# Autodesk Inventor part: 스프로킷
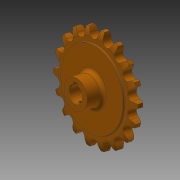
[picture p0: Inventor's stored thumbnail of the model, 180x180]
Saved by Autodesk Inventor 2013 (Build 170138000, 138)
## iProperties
Created: 2016-03
Part Number: 스프로킷
Material: 강철, 탄소
Document SubType Name: Modeling
Designer: mduedu
Density: 7.87 g/cm^3
Mass: 301.818 g
Surface Area: 124.882 cm^2
Volume: 38.3505 cm^3
Author: mduedu
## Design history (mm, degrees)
sketch "스케치1"
  geometry: L1 (0, 5)-(29.5, 5); L2 (29.5, 5)-(29.5, 4.1); L3 (30, 3.6)-(33.625, 3.6); L4 (40, 2)-(40, 0); L5 (40, 0)-(0, 0); L6 (0, 0)-(0, 5); L7 (0, -5)-(29.5, -5); L8 (29.5, -5)-(29.5, -4.1); L9 (30, -3.6)-(33.625, -3.6); L10 (40, -2)-(40, 0); L11 (0, 0)-(0, -5); A1 r 13.5 centre (33.625, -9.9) between (40, 2) and (33.625, 3.6); A2 r 13.5 centre (33.625, 9.9) between (33.625, -3.6) and (40, -2); A3 r 0.5 centre (30, 4.1) between (29.5, 4.1) and (30, 3.6); A4 r 0.5 centre (30, -4.1) between (30, -3.6) and (29.5, -4.1); 2 further points
  constraints: 22 end point, 8 point on circle, 6 symmetric about line, 5 tangent, 4 centre point, 4 parallel, 4 point on line, 1 equal radius, 1 horizontal, 1 perpendicular, 1 other
  dimensions: "d0" = 80 diameter of L4 L6; "d2" = 59 diameter of L2 L6; "d3" = 1.6 vertical distance of L4.start L3.end; "d4" = 3.6 distance from line of L4.end L3; "d5" = 5 distance between parallel lines of L5 L1; "d6" = 13.5 radius of A1; "d15" = 0.5 radius of A3
revolve "회전1" sketch "스케치1" stored, may be unused: angle "d7" = 90 deg
sketch "스케치2" dims "d8" = 65.2, "d11" = 80
  geometry: L1 (0, 0)-(0, 32.6); A1 r 36.57 centre (0, 0) between (-16.231, 32.771) and (0, 36.57); A2 r 3.97 centre (0, 36.57) between (-3.866, 35.665) and (0, 32.6); A3 r 12.7 centre (-16.231, 32.771) between (-3.866, 35.665) and (-5.534, 39.615); A4 r 12.7 centre (16.231, 32.771) between (5.534, 39.615) and (3.866, 35.665); A5 r 3.97 centre (0, 36.57) between (0, 32.6) and (3.866, 35.665); A6 r 40 centre (0, 0) between (5.534, 39.615) and (-5.534, 39.615); 2 further points
  constraints: 12 point on circle, 6 centre point, 4 coincident, 3 symmetric about line, 2 end point, 1 point on line, 1 tangent, 1 vertical, 1 vertical alignment, 7 other
  dimensions: "d10" = 73.14 diameter of A1; "d12" = 12.7 radius of A3
extrude "돌출1" cut sketch "스케치2" stored distance "d13" = 10; taper "d14" = 0 deg
sketch "스케치3"
  geometry: C1 r 11 at (0, 0); 1 further point
  constraints: 1 centre point, 1 coincident
  dimensions: "d19" = 22 diameter of C1
extrude "돌출2" join sketch "스케치3" distance "d20" = 13; taper "d21" = 0 deg
fillet "모깎기1" dims "d22" = 3
sketch "스케치4"
  geometry: L1 (-2, 0)-(2, 0); L2 (2, 0)-(2, 7.8); L3 (2, 7.8)-(-2, 7.8); L4 (-2, 7.8)-(-2, 0); C1 r 6 at (0, 0); 2 further points
  constraints: 8 end point, 2 coincident, 2 parallel, 1 centre point, 1 horizontal, 1 midpoint, 1 perpendicular
  dimensions: "d23" = 12 diameter of C1; "d25" = 4 distance of L2.end L3.end; "d26" = 7.8 distance of L1.end L2.end
extrude "돌출3" cut sketch "스케치4" stored distance "d27" = 8; taper "d28" = 0 deg
chamfer "모따기1" distance "d29" = 0.5; stored, may be unused: second distance "d30" = 2, angle "d31" = 45 deg
node "작업 평면1"
sketch "스케치5"
  geometry: L1 (11, 13)-(-11, 13) reference; 2 further points
  constraints: 1 vertical alignment
  dimensions: "d32" = 4 distance from line of point (0, 9) L1
hole "구멍1" sketch "스케치5" at (0, 9) diameter "d33" = 2.459; stored, may be unused: countersink angle "d37" = 90 deg, drill point angle "d39" = 118 deg; dims "d34" = 6, "d35" = 4, "d36" = 2, "d38" = 8
node "솔리드1"
pattern_circular "원형 패턴1" dims angle "d17" = 360 deg
